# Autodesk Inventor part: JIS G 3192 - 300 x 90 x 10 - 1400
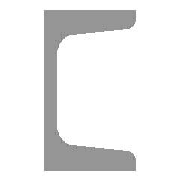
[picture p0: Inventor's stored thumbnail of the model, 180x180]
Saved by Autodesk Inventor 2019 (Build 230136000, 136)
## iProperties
IsCustomPart: 1
Created: 2017-02
Part Number: JIS G 3192 - 300 x 90 x 10 - 1400
Material: 鋼、軟鋼
Description: U 形熱間圧延鋼
Document SubType Name: Modeling
Standard: JIS
Designer: shimont
Standard Revision: 2014
Standards Organization: JIS
Language: ja-JP
Size Designation: 300 x 90 x 10
Categories: <MemberInstance><Categories><Category DisplayName="形鋼" InternalName="089c4875-fa83-4c05-b084-43b9cc11f5ed" Mnemonic="GRDR"><CategoryParameter DisplayName="長さ単位ご
Stock Number: 300 x 90 x 10
Density: 7.85 g/cm^3
Appearance: 半つや出し
Mass: 61264.1 g
Surface Area: 12805.5 cm^2
Volume: 7804.34 cm^3
G_L: 1400.000 mm
G_W: 90.000 mm
G_H: 300.000 mm
_CCFamilyMember: 12
_CCFamilyDisplayName: JIS G 3192 - U 形熱間圧延鋼
_FrameMemberDoc: Frame Member File
_Version: 15.0.0
_GetPNFromCC: 1
Author: shimont
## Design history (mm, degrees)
node "開始平面"
node "終了平面"
sketch "スケッチ"
  geometry: L1 (-23.4, 0)-(-23.4, 150); L2 (-23.4, 150)-(66.6, 150); L3 (66.6, 150)-(66.6, 146.705); L4 (57.928, 137.241)-(3.944, 132.518); L5 (-13.4, 113.59)-(-13.4, 0); L6 (-13.4, 0)-(-23.4, 0); L7 (26.6, 150)-(26.6, 134.5); L8 (66.6, 138)-(66.6, 134.5); L9 (66.6, 134.5)-(26.6, 134.5); L10 (0, 15)-(0, -27); L11 (-5.539, 0)-(16.007, 0); L12 (-23.4, 0)-(-23.4, -150); L13 (-23.4, -150)-(66.6, -150); L14 (66.6, -150)-(66.6, -146.705); L15 (57.928, -137.241)-(3.944, -132.518); L16 (-13.4, -113.59)-(-13.4, 0); L17 (0, 210)-(0, -210) reference; L18 (-41.768, 0)-(86.808, 0) reference; A1 r 19 centre (5.6, 113.59) between (3.944, 132.518) and (-13.4, 113.59); A2 r 19 centre (5.6, -113.59) between (-13.4, -113.59) and (3.944, -132.518); A3 r 9.5 centre (57.1, 146.705) between (57.928, 137.241) and (66.6, 146.705); A4 r 9.5 centre (57.1, -146.705) between (66.6, -146.705) and (57.928, -137.241); 5 further points
  constraints: 32 end point, 12 point on line, 8 point on circle, 8 tangent, 6 symmetric about line, 4 centre point, 4 parallel, 3 collinear, 3 perpendicular, 2 equal radius, 5 other
  dimensions: "d0" = 10 distance between parallel lines of L1 L5 (= G_T); "d1" = 150 distance between parallel lines of L6 L2 (= 0.5 x G_H); "d2" = 90 distance between parallel lines of L3 L1 (= G_W); "d3" = 15.5 distance of L2.end L8.end (= G_T1); "d4" = 40 distance of L7.start L2.end (= G_C); "d5" = 3.4996 distance of L8.start L8.end (computed from G_NG, G_C); "d23" = 19 radius of A1 (= G_IR); "d24" = 9.5 radius of A3 (= G_ER); "d25" = 23.4 distance between parallel lines of L10 L12 (= ey)
extrude "ボディ" new body sketch "スケッチ" stored distance "d6" = 1400 (= G_L); taper "d7" = 0 deg
node "Driven Length"
  sketch "Sketch3"
    geometry: L1 (0, 0)-(10, 0) reference
    constraints: 2 end point, 1 horizontal
  workplane "Work Plane3"
  sketch "Sketch4"
    geometry: L1 (-2, 0)-(12, 0) reference; L2 (-2, 1400)-(12, 1400) reference
    dimensions: "d29" = 1400 distance between parallel lines of L1 L2 (derived)
node "作業平面4"
feature "分割1"
node "作業平面5"
feature "分割2"
body "Solid1"
other parameters: "G_W" = 90 [user parameter; used in 1 equation term], "G_H" = 300 [user parameter; used in 1 equation term], "G_T" = 10 [user parameter; used in 1 equation term], "G_T1" = 15.5 [user parameter; used in 1 equation term], "G_NG" = 0.8749 [user parameter; used in 1 equation term], "G_ER" = 9.5 [user parameter; used in 1 equation term], "G_IR" = 19 [user parameter; used in 1 equation term], "G_C" = 40 [user parameter; used in 2 equation terms], "G_L" = 1400 (= d29) [user parameter; used in 1 equation term], "ey" = 23.4 [user parameter; used in 1 equation term], "G_OFFSET_START" = 0 [user parameter; used in 1 equation term], "G_OFFSET_END" = 0 [user parameter; used in 1 equation term], "d26" = 0 (computed from G_OFFSET_START), "d28" = 90 deg
